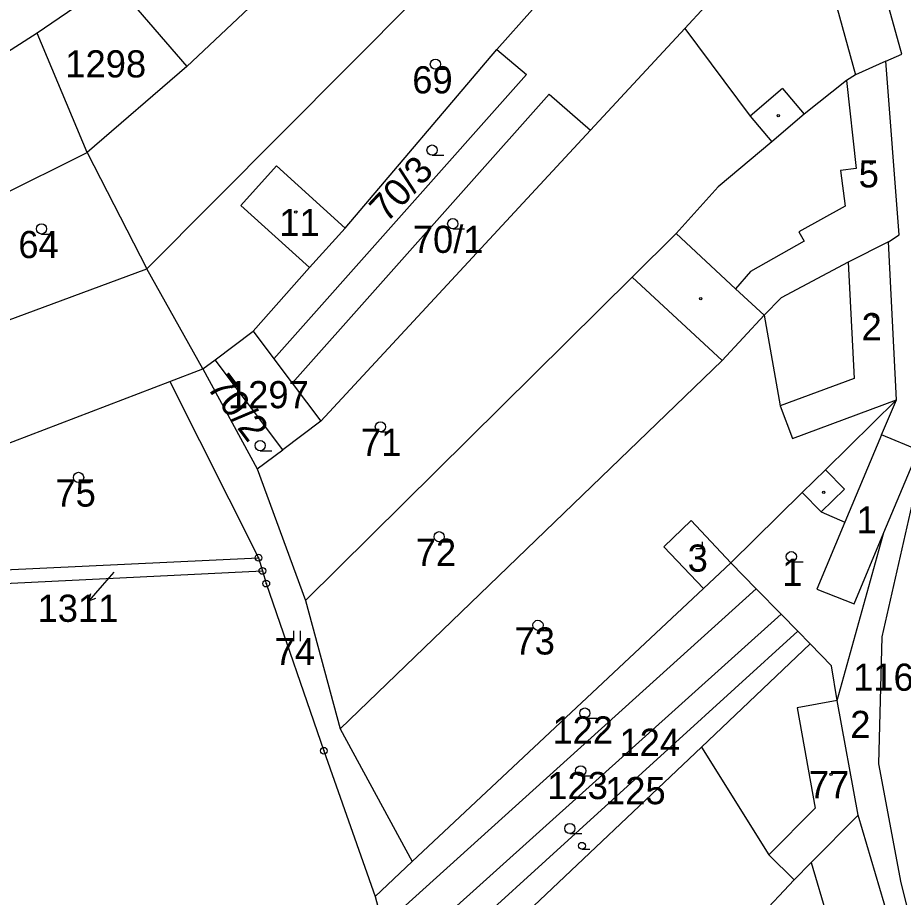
# Model space of a CAD drawing. Extents: x -564516 to -563466, y -1163913 to -1163170.
# Drawn here: x -564277.2 to -564146.8, y -1163610.3 to -1163480.8 of the extents above; entities that cross this region are included whole.
import ezdxf

# ---------------------------------------------------------------- set-up
doc = ezdxf.new("R2010")
doc.units = 0
for name, color, linetype in [('Hranice parcel', 7, 'Continuous'), ('Parcelní čísla', 7, 'Continuous'), ('Pop  PČ popisy', 7, 'Continuous'), ('Vnitřní kresba', 7, 'Continuous'), ('Značky bodu BP', 7, 'Continuous'), ('Značky budov', 7, 'Continuous'), ('Značky kultur', 7, 'Continuous')]:
    doc.layers.add(name, color=color, linetype=linetype)

msp = doc.modelspace()

# ---------------------------------------------------------------- linework, layer by layer
at = {"layer": 'Hranice parcel'}
for p, q in [((-564252.3, -1163487.96), (-564223.24, -1163460.61)), ((-564263.15, -1163475.4), (-564274.36, -1163483.08)), ((-564263.15, -1163475.4), (-564252.3, -1163487.96)), ((-564274.36, -1163483.08), (-564280.15, -1163486.75)), ((-564266.98, -1163500.64), (-564274.36, -1163483.08)), ((-564192.86, -1163497.36), (-564178.97, -1163482.37)), ((-564228.99, -1163511.77), (-564206.67, -1163485.5)), ((-564252.3, -1163487.96), (-564266.98, -1163500.64)), ((-564232.6, -1163540.23), (-564192.86, -1163497.36)), ((-564312.09, -1163523), (-564266.98, -1163500.64)), ((-564266.98, -1163500.64), (-564258.23, -1163517.79)), ((-564234.26, -1163517.6), (-564228.99, -1163511.77)), ((-564147.82, -1163537.06), (-564148.99, -1163513.81)), ((-564318.98, -1163540.26), (-564258.23, -1163517.79)), ((-564249.96, -1163532.51), (-564258.23, -1163517.79)), ((-564242.57, -1163526.96), (-564234.26, -1163517.6)), ((-564234.83, -1163566.63), (-564186.72, -1163519.03)), ((-564186.72, -1163519.03), (-564173.48, -1163531.3)), ((-564173.48, -1163531.3), (-564167.29, -1163524.62)), ((-564248.17, -1163531.16), (-564242.57, -1163526.96)), ((-564242.57, -1163526.96), (-564239.51, -1163531.04)), ((-564249.96, -1163532.51), (-564248.17, -1163531.16)), ((-564238.2, -1163544.43), (-564248.17, -1163531.16)), ((-564239.51, -1163531.04), (-564236.81, -1163534.63)), ((-564229.74, -1163585.51), (-564173.48, -1163531.3)), ((-564254.84, -1163534.38), (-564249.96, -1163532.51)), ((-564249.96, -1163532.51), (-564241.94, -1163547.25)), ((-564301.49, -1163552.26), (-564254.84, -1163534.38)), ((-564254.84, -1163534.38), (-564241.77, -1163560.32)), ((-564236.81, -1163534.63), (-564232.6, -1163540.23)), ((-564232.6, -1163540.23), (-564238.2, -1163544.43)), ((-564241.94, -1163547.25), (-564238.2, -1163544.43)), ((-564149.67, -1163556.63), (-564144.59, -1163544.5)), ((-564241.94, -1163547.25), (-564234.83, -1163566.63)), ((-564161.69, -1163550.72), (-564172.19, -1163561.06)), ((-564156.54, -1163581.37), (-564149.67, -1163556.63)), ((-564285.63, -1163562.43), (-564241.77, -1163560.32)), ((-564241.77, -1163560.32), (-564241.19, -1163562.27)), ((-564176.22, -1163564.84), (-564172.19, -1163561.06)), ((-564172.19, -1163561.06), (-564168.46, -1163564.89)), ((-564284.23, -1163564.35), (-564241.19, -1163562.27)), ((-564223.46, -1163614.55), (-564168.46, -1163564.89)), ((-564219.12, -1163605.07), (-564176.22, -1163564.84)), ((-564168.46, -1163564.89), (-564164.82, -1163568.62)), ((-564234.83, -1163566.63), (-564229.74, -1163585.51)), ((-564222.05, -1163620.11), (-564164.82, -1163568.62)), ((-564164.82, -1163568.62), (-564162.36, -1163571.14)), ((-564220.56, -1163624.11), (-564162.36, -1163571.14)), ((-564162.36, -1163571.14), (-564160.53, -1163573.02)), ((-564160.53, -1163573.02), (-564176.54, -1163588.25)), ((-564153.46, -1163598.26), (-564156.54, -1163581.37)), ((-564229.74, -1163585.51), (-564219.12, -1163605.07)), ((-564219.45, -1163628.81), (-564176.54, -1163588.25)), ((-564147.6, -1163618.07), (-564153.46, -1163598.26)), ((-564224.59, -1163610.2), (-564219.12, -1163605.07)), ((-564162.89, -1163607.78), (-564169.68, -1163615)), ((-564224.59, -1163610.2), (-564223.46, -1163614.55))]:
    msp.add_line(p, q, dxfattribs=at)
for points in [[(-564258.23, -1163517.79), (-564218.53, -1163477.88), (-564191.06, -1163449.86), (-564183.85, -1163444.38)], [(-564175.84, -1163455.1), (-564185.67, -1163461.88), (-564206.67, -1163485.5)], [(-564152.39, -1163466.83), (-564159.05, -1163470.31), (-564175.97, -1163479.14), (-564178.97, -1163482.37)], [(-564149.38, -1163487.2), (-564147.05, -1163486.16), (-564152.39, -1163466.83)], [(-564178.97, -1163482.37), (-564169.36, -1163495.27), (-564166.17, -1163499.05)], [(-564206.67, -1163485.5), (-564202.3, -1163489.15), (-564239.51, -1163531.04)], [(-564149.38, -1163487.2), (-564153.84, -1163489.19), (-564155.18, -1163490.03), (-564161.39, -1163495.02), (-564166.17, -1163499.05)], [(-564148.99, -1163513.81), (-564147.43, -1163512.77), (-564149.38, -1163487.2)], [(-564236.81, -1163534.63), (-564198.98, -1163492.04), (-564192.86, -1163497.36)], [(-564166.17, -1163499.05), (-564174.08, -1163505.72), (-564180.27, -1163512.59), (-564186.72, -1163519.03)], [(-564228.99, -1163511.77), (-564239.11, -1163502.63), (-564244.38, -1163508.46), (-564234.26, -1163517.6)], [(-564148.99, -1163513.81), (-564154.95, -1163516.79), (-564164.8, -1163522.06), (-564167.29, -1163524.62)], [(-564167.29, -1163524.62), (-564164.97, -1163537.97), (-564163.15, -1163542.76), (-564147.82, -1163537.06)], [(-564147.82, -1163537.06), (-564158.27, -1163547.36), (-564161.69, -1163550.72)], [(-564144.59, -1163544.5), (-564150.02, -1163542.22), (-564147.82, -1163537.06)], [(-564141.75, -1163629.73), (-564147.11, -1163608.19), (-564150.44, -1163590.7), (-564149.91, -1163571.99), (-564143.77, -1163544.97)], [(-564161.69, -1163550.72), (-564158.89, -1163553.57), (-564155.42, -1163555.11), (-564159.56, -1163564.98), (-564154.07, -1163567.12), (-564149.67, -1163556.63)], [(-564172.19, -1163561.06), (-564178.06, -1163554.85), (-564182.1, -1163558.74), (-564176.22, -1163564.84)], [(-564241.19, -1163562.27), (-564240.63, -1163564.13), (-564232.14, -1163588.76), (-564224.59, -1163610.2)], [(-564156.54, -1163581.37), (-564157.39, -1163576.24), (-564160.53, -1163573.02)], [(-564176.54, -1163588.25), (-564166.61, -1163604.1), (-564162.89, -1163607.78)], [(-564162.89, -1163607.78), (-564160.37, -1163605.23), (-564153.46, -1163598.26)]]:
    msp.add_lwpolyline(points, dxfattribs=at)
at = {"layer": 'Pop  PČ popisy'}
for p, q in [((-564263.06, -1163562.43), (-564264.78, -1163564.42)), ((-564264.78, -1163564.42), (-564266.75, -1163566.69)), ((-564266.75, -1163566.69), (-564266.47, -1163565.6)), ((-564266.75, -1163566.69), (-564265.71, -1163566.26))]:
    msp.add_line(p, q, dxfattribs=at)
at = {"layer": 'Vnitřní kresba'}
for p, q in [((-564159.05, -1163470.31), (-564153.84, -1163489.19)), ((-564164.58, -1163491.24), (-564169.36, -1163495.27)), ((-564164.58, -1163491.24), (-564161.39, -1163495.02)), ((-564171.52, -1163520.7), (-564180.27, -1163512.59)), ((-564154.95, -1163516.79), (-564154.06, -1163533.91)), ((-564167.29, -1163524.62), (-564171.52, -1163520.7)), ((-564154.06, -1163533.91), (-564164.97, -1163537.97)), ((-564150.02, -1163542.22), (-564155.42, -1163555.11)), ((-564158.27, -1163547.36), (-564155.47, -1163550.21)), ((-564158.89, -1163553.57), (-564155.47, -1163550.21)), ((-564156.54, -1163581.37), (-564162.46, -1163582.44)), ((-564162.46, -1163582.44), (-564159.77, -1163597.2)), ((-564159.77, -1163597.2), (-564166.61, -1163604.1)), ((-564160.37, -1163605.23), (-564156.31, -1163618.94))]:
    msp.add_line(p, q, dxfattribs=at)
msp.add_lwpolyline([(-564155.18, -1163490.03), (-564153.74, -1163502.99), (-564156.04, -1163503.3), (-564155.38, -1163508.57), (-564162.18, -1163512.33), (-564161.43, -1163513.69), (-564169.31, -1163518.15), (-564171.52, -1163520.7)], dxfattribs=at)
at = {"layer": 'Značky bodu BP'}
for centre, radius in [((-564241.77, -1163560.32), 0.5), ((-564241.77, -1163560.32), 0.0303), ((-564241.19, -1163562.27), 0.5), ((-564241.19, -1163562.27), 0.0303), ((-564240.63, -1163564.13), 0.5), ((-564240.63, -1163564.13), 0.0303), ((-564232.14, -1163588.76), 0.5), ((-564232.14, -1163588.76), 0.0303)]:
    msp.add_circle(centre, radius, dxfattribs=at)
at = {"layer": 'Značky budov'}
for centre in [(-564165.22, -1163495.22), (-564151.53, -1163502.24), (-564236.27, -1163509.41), (-564176.65, -1163522.17), (-564151.07, -1163524.75), (-564158.52, -1163550.68), (-564152.39, -1163553.2), (-564157.45, -1163592.21)]:
    msp.add_circle(centre, 0.175, dxfattribs=at)
at = {"layer": 'Značky kultur'}
for p, q in [((-564215.72, -1163488.39), (-564213.97, -1163488.39)), ((-564216.21, -1163501.04), (-564214.46, -1163501.04)), ((-564213.16, -1163511.88), (-564211.41, -1163511.88)), ((-564273.73, -1163512.65), (-564271.98, -1163512.65)), ((-564223.82, -1163541.79), (-564222.07, -1163541.79)), ((-564241.53, -1163544.57), (-564239.78, -1163544.57)), ((-564268.26, -1163549.25), (-564266.51, -1163549.25)), ((-564215.17, -1163557.98), (-564213.42, -1163557.98)), ((-564177.36, -1163558.99), (-564176.36, -1163558.99)), ((-564176.36, -1163558.99), (-564176.36, -1163557.99)), ((-564163.3, -1163560.92), (-564161.55, -1163560.92)), ((-564236.57, -1163572.6), (-564236.57, -1163571.1)), ((-564235.57, -1163572.6), (-564235.57, -1163571.1)), ((-564200.61, -1163571.03), (-564198.86, -1163571.03)), ((-564193.7, -1163583.95), (-564191.95, -1163583.95)), ((-564194.32, -1163592.46), (-564192.57, -1163592.46)), ((-564195.92, -1163600.96), (-564194.17, -1163600.96)), ((-564194.13, -1163603.25), (-564192.95, -1163603.25))]:
    msp.add_line(p, q, dxfattribs=at)
for centre, radius in [((-564215.72, -1163487.64), 0.75), ((-564216.21, -1163500.29), 0.75), ((-564213.16, -1163511.13), 0.75), ((-564273.73, -1163511.9), 0.75), ((-564223.82, -1163541.04), 0.75), ((-564241.53, -1163543.82), 0.75), ((-564268.26, -1163548.5), 0.75), ((-564215.17, -1163557.23), 0.75), ((-564163.3, -1163560.17), 0.75), ((-564200.61, -1163570.28), 0.75), ((-564193.7, -1163583.2), 0.75), ((-564194.32, -1163591.71), 0.75), ((-564195.92, -1163600.21), 0.75), ((-564194.13, -1163602.75), 0.502)]:
    msp.add_circle(centre, radius, dxfattribs=at)

# ---------------------------------------------------------------- texts
at = {"layer": 'Parcelní čísla'}
for s, p in [('1298', (-564270.21, -1163489.59)), ('69', (-564219.12, -1163491.94)), ('5', (-564153.39, -1163505.79)), ('11', (-564238.71, -1163512.96)), ('70/1', (-564219.04, -1163515.43)), ('64', (-564277.13, -1163516.2)), ('2', (-564152.96, -1163528.3)), ('1297', (-564246.26, -1163538.31)), ('71', (-564226.69, -1163545.34)), ('75', (-564271.67, -1163552.8)), ('1', (-564153.71, -1163556.75)), ('72', (-564218.61, -1163561.53)), ('3', (-564178.57, -1163562.38)), ('1', (-564164.64, -1163564.47)), ('1311', (-564274.3, -1163569.77)), ('73', (-564204.07, -1163574.58)), ('74', (-564239.39, -1163576.15)), ('1163/1', (-564154.2, -1163579.92)), ('122', (-564198.48, -1163587.69)), ('2', (-564154.62, -1163586.88)), ('124', (-564188.61, -1163589.51)), ('123', (-564199.24, -1163595.88)), ('125', (-564190.73, -1163596.63)), ('77', (-564160.72, -1163595.76))]:
    msp.add_text(s, height=4, dxfattribs=at).set_placement(p)
for s, rotation, p in [('70/3', 47, (-564222.89, -1163511.12)), ('70/2', 307, (-564249.49, -1163535.23))]:
    msp.add_text(s, height=4, rotation=rotation, dxfattribs=at).set_placement(p)

doc.saveas('drawing.dxf')
